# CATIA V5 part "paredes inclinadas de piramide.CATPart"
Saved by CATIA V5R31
Part number: paredes inclinadas de piramide
Bounding box of the stored display mesh (mm): x 0 to 3.3, y -81.6 to 81.6, z 0 to 130
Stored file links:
  C:\Users\189361\Desktop\piezas del comedero\piezas del comedero\paredes inclinadas de piramide.CATPart
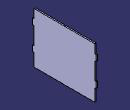
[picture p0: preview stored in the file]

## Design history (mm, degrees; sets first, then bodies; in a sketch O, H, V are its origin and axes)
Body1 (main body)
  Sketch1 on yz-plane, origin (0, 0, 0), H (0, 1, 0), V (0, 0, 1)
    line L1 (0, 0) -> (-78.3, 0)
    point P1 (-78.3, 0)
    line L2 (-78.3, 0) -> (-78.3, 32.35)
    point P2 (-78.3, 32.35)
    line L3 (-78.3, 32.35) -> (-81.6, 32.35)
    point P3 (-81.6, 32.35)
    line L4 (-81.6, 32.35) -> (-81.6, 47.65)
    point P4 (-81.6, 47.65)
    line L5 (-81.6, 47.65) -> (-78.3, 47.65)
    point P5 (-78.3, 47.65)
    line L6 (-78.3, 47.65) -> (-78.3, 92.35)
    point P6 (-78.3, 92.35)
    construction line L7 (-102.2606, 40) -> (-59.1762, 40)
    point P8 (-59.1762, 40)
    axis line L8 (-118.8714, 70) -> (-49.8326, 70)
    point P10 (-49.8326, 70)
    point P11 (-78.3, 107.65)
    point P12 (-81.6, 107.65)
    point P13 (-81.6, 92.35)
    point P14 (-78.3, 92.35)
    point P15 (-59.1762, 100)
    line L9 (-78.3, 107.65) -> (-81.6, 107.65)
    line L10 (-81.6, 107.65) -> (-81.6, 92.35)
    line L11 (-81.6, 92.35) -> (-78.3, 92.35)
    line L12 (-78.3, 107.65) -> (-78.3, 130)
    point P16 (-78.3, 130)
    line L13 (-78.3, 130) -> (0, 130)
    point P17 (0, 130)
    point P18 (0, 0)
    point P19 (78.3, 0)
    point P20 (78.3, 32.35)
    point P21 (81.6, 32.35)
    point P22 (81.6, 47.65)
    point P23 (78.3, 47.65)
    point P24 (78.3, 92.35)
    point P25 (59.1762, 40)
    point P26 (49.8326, 70)
    point P27 (78.3, 107.65)
    point P28 (81.6, 107.65)
    point P29 (81.6, 92.35)
    point P30 (78.3, 92.35)
    point P31 (59.1762, 100)
    point P32 (78.3, 130)
    point P33 (0, 130)
    line L14 (0, 0) -> (78.3, 0)
    line L15 (78.3, 0) -> (78.3, 32.35)
    line L16 (78.3, 32.35) -> (81.6, 32.35)
    line L17 (81.6, 32.35) -> (81.6, 47.65)
    line L18 (81.6, 47.65) -> (78.3, 47.65)
    line L19 (78.3, 47.65) -> (78.3, 92.35)
    line L20 (78.3, 107.65) -> (81.6, 107.65)
    line L21 (81.6, 107.65) -> (81.6, 92.35)
    line L22 (81.6, 92.35) -> (78.3, 92.35)
    line L23 (78.3, 107.65) -> (78.3, 130)
    line L24 (78.3, 130) -> (0, 130)
    distance L7 L5 = 7.65
    length L4 = 15.3
    distance L7 L1 = 40
    distance L8 L7 = 30
    distance L13 L1 = 130
    length L3 = 3.3
    distance V L2 = 78.3
    horizontal: L1 H, L5 H, L3 H, L7 H, L8 H, L13 H
    vertical: L2 V, L4 V, L6 V, L12 V
    coincidence: P5 L2, P2 L6, P6 L2, P6 P14, P17 V, O P18, P17 P33, P24 P30
    symmetry: P2 P11 L8, P3 P12 L8, P4 P13 L8, P5 P14 L8, P8 P15 L8, L3 L9 L8, L4 L10 L8, L5 L11 L8, O P18 V, P1 P19 V, P2 P20 V, P3 P21 V, P4 P22 V, P5 P23 V, P6 P24 V, P8 P25 V, P10 P26 V, P11 P27 V, P12 P28 V, P13 P29 V, P14 P30 V, P15 P31 V, P16 P32 V, P17 P33 V, L1 L14 V, L2 L15 V, L3 L16 V, L4 L17 V, L5 L18 V, L6 L19 V, L9 L20 V, L10 L21 V, L11 L22 V, L12 L23 V, L13 L24 V
  Pad1: profile Sketch1, direction (1, 0, 0), length 3.3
